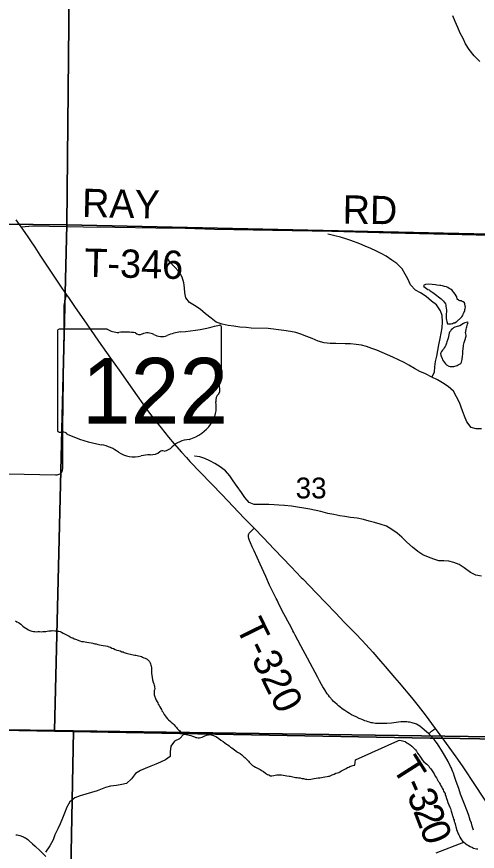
# Model space of a CAD drawing. Extents: x -8.8 to 41.4, y 0 to 34.6.
# Drawn here: x 7.271 to 8.197, y 18.372 to 20.049 of the extents above; entities that cross this region are included whole.
import ezdxf

# ---------------------------------------------------------------- set-up
doc = ezdxf.new("R2010")
doc.units = 0
for name, color, linetype in [('GM_X_City_Street', 7, 'Continuous'), ('GM_X_Corporation', 7, 'Continuous'), ('GM_X_Minor_Lake', 7, 'Continuous'), ('GM_X_Minor_River', 7, 'Continuous'), ('GM_X_Section_Text', 7, 'Continuous'), ('GM_X_State_Route', 7, 'Continuous'), ('GM_X_Township_Road', 7, 'Continuous'), ('GM_X_Township_Text', 7, 'Continuous'), ('GM_X_Unincorporated_Location', 7, 'Continuous')]:
    doc.layers.add(name, color=color, linetype=linetype)

msp = doc.modelspace()

# ---------------------------------------------------------------- linework, layer by layer
at = {"layer": 'GM_X_City_Street'}
for p, q in [((7.4526, 19.4206), (7.3561, 19.4206)), ((7.6825, 19.3209), (7.6825, 19.4256)), ((7.3529, 19.4172), (7.3529, 19.2171)), ((7.6824, 19.3209), (7.6825, 19.3209))]:
    msp.add_line(p, q, dxfattribs=at)
for centre, major_axis, start_param, end_param in [((7.3567, 19.4176), (0.00382, 0), 1.712693, 3.28349), ((7.4756, 19.4439), (0.037, 0), 4.042523, 4.731795), ((7.5651, 19.6935), (0.3495, 0), 4.814394, 5.042369), ((7.6788, 19.426), (0.00367, 0), 6.141152, 7.989035), ((7.4879, 19.3083), (0.133, 0), 1.404758, 1.657858), ((7.5181, 19.4187), (0.0107, 0), 3.836095, 5.185415), ((7.5338, 19.3955), (0.0222, 0), 0.950623, 2.079405), ((7.5624, 19.4273), (0.0267, 0), 4.081561, 5.145723), ((7.6096, 19.3595), (0.0703, 0), 1.699011, 2.107814), ((7.6785, 19.3205), (0.00393, 0), 5.05454, 6.418171), ((7.6816, 19.3132), (0.00568, 0), 1.883978, 3.671073), ((7.6455, 19.3), (0.0341, 0), 5.934695, 6.695948), ((7.6956, 19.2771), (0.0248, 0), 2.387724, 3.262537), ((7.5846, 19.2638), (0.0874, 0), 5.101752, 6.440018), ((7.3567, 19.2166), (0.00385, 0), 3.00124, 4.508301), ((7.3573, 19.2371), (0.0294, 0), 4.665946, 4.897461), ((7.3633, 19.2055), (0.0106, 0), 0.519207, 1.627899), ((7.4971, 19.3853), (0.2524, 0), 4.195997, 4.488961), ((7.4219, 19.1272), (0.079, 0), 0.823519, 1.323587), ((7.6215, 19.1609), (0.0479, 0), 1.647645, 2.488434), ((7.5073, 19.2045), (0.0501, 0), 4.026481, 4.996735), ((7.5362, 19.1353), (0.0412, 0), 1.495662, 1.94098), ((7.5399, 19.1896), (0.0267, 0), 4.691044, 5.507374), ((7.564, 19.1702), (0.00752, 0), 1.147584, 2.315152), ((7.5608, 19.1977), (0.0282, 0), 4.937069, 5.64225)]:
    msp.add_ellipse(centre, major_axis=major_axis, ratio=0.8, start_param=start_param, end_param=end_param, dxfattribs=at)
at = {"layer": 'GM_X_Corporation'}
for points in [[(6.8788, 18.6215), (8.1022, 18.5991), (8.1227, 18.5988), (8.3593, 18.595), (8.7626, 18.5884), (8.7926, 18.589), (8.8166, 18.5892), (8.8254, 18.5889), (8.8358, 18.5879), (8.8426, 18.587), (8.8536, 18.5853), (8.8632, 18.5843), (8.8658, 18.5843), (8.8715, 18.5846), (8.8767, 18.5853), (8.8942, 18.5896), (8.9, 18.5906), (8.9, 20.9)], [(6.3705, 18.3923), (6.3731, 18.628), (7.3471, 18.6145), (7.385, 18.614), (7.3641, 17.5315), (6.3609, 17.5464), (6.3656, 17.9584)], [(8.9, 14.1), (8.9, 18.5906), (8.8942, 18.5896), (8.8767, 18.5853), (8.8715, 18.5846), (8.8658, 18.5843), (8.8632, 18.5843), (8.8536, 18.5853), (8.8426, 18.587), (8.8358, 18.5879), (8.8254, 18.5889), (8.8166, 18.5892), (8.7926, 18.589), (8.7626, 18.5884), (8.3593, 18.595), (8.1227, 18.5988), (8.1022, 18.5991), (6.8788, 18.6215)]]:
    msp.add_lwpolyline(points, dxfattribs=at)
for points in [[(6.3701, 20.6506), (7.3817, 20.6407), (7.3719, 19.6303), (6.3565, 19.6406)], [(7.3817, 20.6407), (8.3787, 20.6214), (8.3714, 19.6082), (7.3719, 19.6303)], [(7.3719, 19.6303), (7.3471, 18.6145), (6.3731, 18.628), (6.3474, 18.629), (6.3565, 19.6406)], [(8.3714, 19.6082), (8.3651, 18.5999), (7.385, 18.614), (7.3471, 18.6145), (7.3719, 19.6303)], [(7.385, 18.614), (8.3651, 18.5999), (8.3581, 17.5144), (7.3641, 17.5315)]]:
    msp.add_lwpolyline(points, close=True, dxfattribs=at)
at = {"layer": 'GM_X_Minor_Lake'}
for points in [[(8.1561, 19.4365), (8.1641, 19.4433), (8.1661, 19.4455), (8.1673, 19.4477), (8.1685, 19.4504), (8.1693, 19.4526), (8.1718, 19.4579), (8.1718, 19.4601), (8.1727, 19.4624), (8.1731, 19.4647), (8.1728, 19.4673), (8.1721, 19.4715), (8.171, 19.4738), (8.1688, 19.4754), (8.1665, 19.4766), (8.1642, 19.4774), (8.1619, 19.4779), (8.1589, 19.4791), (8.1566, 19.481), (8.156, 19.4856), (8.1545, 19.4879), (8.1527, 19.4914), (8.1497, 19.4945), (8.1478, 19.4968), (8.1464, 19.4991), (8.143, 19.5011), (8.1407, 19.5027), (8.138, 19.5043), (8.135, 19.5059), (8.1312, 19.5067), (8.127, 19.508), (8.1239, 19.5084), (8.1213, 19.5085), (8.1159, 19.5094), (8.1128, 19.5098), (8.1059, 19.5108), (8.0979, 19.511), (8.0925, 19.5103), (8.089, 19.5085), (8.0893, 19.5062), (8.092, 19.5046), (8.0946, 19.5023), (8.0972, 19.5007), (8.1003, 19.4995), (8.1025, 19.4979), (8.1056, 19.496), (8.1078, 19.4944), (8.1131, 19.4905), (8.1157, 19.4881), (8.1191, 19.4858), (8.1214, 19.4838), (8.124, 19.4815), (8.127, 19.4791), (8.1292, 19.4768), (8.1307, 19.4744), (8.133, 19.4717), (8.1337, 19.4691), (8.134, 19.4668), (8.1349, 19.4588), (8.1346, 19.4482), (8.1342, 19.4455), (8.1345, 19.4421), (8.1352, 19.439), (8.1355, 19.436), (8.1373, 19.4318)], [(8.1373, 19.4318), (8.1396, 19.4313), (8.1419, 19.4316), (8.1442, 19.4316), (8.1469, 19.4323), (8.1492, 19.4334), (8.1515, 19.4337), (8.1547, 19.4355), (8.1561, 19.4365)], [(8.1617, 19.4275), (8.1612, 19.4272), (8.1589, 19.4265), (8.1566, 19.4262), (8.1519, 19.4248), (8.1492, 19.4233), (8.1469, 19.4215), (8.1445, 19.4196), (8.1429, 19.417), (8.1413, 19.4148), (8.1405, 19.4125), (8.1391, 19.4057), (8.1383, 19.4027), (8.1375, 19.4005), (8.1358, 19.3952), (8.1353, 19.3929), (8.1337, 19.3884), (8.1321, 19.3858), (8.1305, 19.3832), (8.1293, 19.3809), (8.1273, 19.3783), (8.1253, 19.3761), (8.1237, 19.3735), (8.1232, 19.3712), (8.1235, 19.3685), (8.1243, 19.3662), (8.1264, 19.3616), (8.1271, 19.3593), (8.1308, 19.3535), (8.1331, 19.3512), (8.1353, 19.3489), (8.1399, 19.3465), (8.1422, 19.3457), (8.1471, 19.3455), (8.1495, 19.3459), (8.1564, 19.348), (8.1588, 19.349), (8.1615, 19.3505), (8.1638, 19.352), (8.165, 19.3542), (8.1659, 19.3572), (8.1667, 19.3595), (8.1668, 19.3621), (8.1673, 19.3652), (8.1673, 19.3674), (8.1678, 19.3697), (8.168, 19.3769), (8.1684, 19.3803), (8.1685, 19.3826), (8.169, 19.386), (8.169, 19.3887), (8.1699, 19.3913), (8.1707, 19.3943), (8.1716, 19.3977), (8.1724, 19.4), (8.1741, 19.4045), (8.1745, 19.4067), (8.1746, 19.409), (8.1739, 19.4117), (8.1735, 19.414), (8.1736, 19.4163), (8.1745, 19.4208), (8.1753, 19.4234), (8.1758, 19.4257), (8.1766, 19.428), (8.1774, 19.4306), (8.1787, 19.434)], [(8.1787, 19.434), (8.1764, 19.4348), (8.1718, 19.4334), (8.1694, 19.4323), (8.1617, 19.4275)]]:
    msp.add_lwpolyline(points, dxfattribs=at)
at = {"layer": 'GM_X_Minor_River'}
for points in [[(8.202, 19.9587), (8.1904, 19.97), (8.1808, 19.9827), (8.1734, 19.9942), (8.1683, 20.0045), (8.1628, 20.0153), (8.1581, 20.0267), (8.1526, 20.039), (8.1479, 20.0501)], [(8.1053, 19.3246), (8.1108, 19.3344), (8.1118, 19.3453), (8.1127, 19.3559), (8.1156, 19.3665), (8.1173, 19.3782), (8.1194, 19.3896), (8.1223, 19.4017), (8.1244, 19.413), (8.1261, 19.4236), (8.1271, 19.4357), (8.1266, 19.4479), (8.1233, 19.4574), (8.1148, 19.4697), (8.1051, 19.4771), (8.0943, 19.4864), (8.083, 19.4935), (8.0729, 19.4993), (8.0628, 19.5101), (8.057, 19.5216), (8.0518, 19.5316), (8.0456, 19.542), (8.0352, 19.5528), (8.025, 19.5594), (8.0138, 19.5672), (8.0037, 19.5727), (7.9928, 19.5782), (7.9826, 19.583), (7.9717, 19.5877), (7.9608, 19.5921), (7.943, 19.5989), (7.9325, 19.6021), (7.9219, 19.6057), (7.9102, 19.6086), (7.8996, 19.6107), (7.8962, 19.6115)], [(8.2051, 19.2203), (8.1948, 19.2205), (8.1843, 19.2234), (8.1758, 19.2349), (8.1714, 19.246), (8.1671, 19.2567), (8.1609, 19.2735), (8.1554, 19.285), (8.1488, 19.2961), (8.1387, 19.3054), (8.1267, 19.3132), (8.117, 19.3187), (8.1053, 19.3246), (8.0929, 19.3309), (8.0813, 19.336), (8.0707, 19.3416), (8.0595, 19.3486), (8.0497, 19.3537), (8.0384, 19.3592), (8.0271, 19.3644), (8.0162, 19.3691), (8.0057, 19.3739), (7.9948, 19.3783), (7.9846, 19.3822), (7.9744, 19.3858), (7.9642, 19.3883), (7.9532, 19.39), (7.9419, 19.391), (7.9316, 19.3912), (7.9127, 19.3919), (7.9009, 19.3921), (7.8892, 19.3931), (7.8767, 19.3968), (7.8651, 19.4019), (7.8545, 19.4063), (7.8421, 19.4107), (7.8319, 19.4139), (7.8217, 19.416), (7.8081, 19.4178), (7.7971, 19.4195), (7.7872, 19.4208), (7.7766, 19.4222), (7.7425, 19.4228), (7.7323, 19.4238), (7.7194, 19.4248), (7.7073, 19.4265), (7.6963, 19.4278), (7.6838, 19.4307), (7.6722, 19.4351), (7.6617, 19.4429), (7.6508, 19.4518), (7.6396, 19.4608), (7.6284, 19.4682), (7.6182, 19.4741), (7.6112, 19.4837), (7.6091, 19.4936), (7.6085, 19.5038), (7.6072, 19.5137), (7.6036, 19.5252), (7.5977, 19.5359), (7.5873, 19.5464), (7.5784, 19.5568), (7.5721, 19.5667), (7.5706, 19.5679)], [(8.2057, 18.9248), (8.194, 18.9266), (8.1831, 18.9317), (8.1704, 18.941), (8.1606, 18.948), (8.1501, 18.952), (8.1399, 18.9549), (8.1296, 18.9551), (8.1198, 18.9556), (8.1096, 18.9585), (8.0987, 18.9625), (8.0874, 18.9672), (8.0776, 18.9739), (8.0668, 18.9828), (8.0556, 18.9929), (8.0455, 19.0029), (8.0358, 19.0111), (8.0249, 19.0185), (8.0141, 19.0251), (8.0016, 19.0291), (7.9903, 19.0324), (7.9797, 19.0352), (7.968, 19.0381), (7.9552, 19.041), (7.9423, 19.0424), (7.9309, 19.0441), (7.9203, 19.0458), (7.9082, 19.0483), (7.8965, 19.0505), (7.8822, 19.0541), (7.8603, 19.0591), (7.8482, 19.0612), (7.8357, 19.063), (7.8232, 19.0651), (7.8096, 19.0665), (7.7982, 19.0671), (7.7887, 19.0676), (7.7781, 19.0682), (7.7686, 19.0688), (7.7591, 19.0686), (7.7481, 19.0684), (7.7383, 19.0728), (7.7294, 19.0828), (7.7231, 19.0928), (7.7139, 19.1043), (7.7061, 19.1162), (7.6995, 19.1258), (7.6905, 19.1358), (7.6801, 19.144), (7.6692, 19.151), (7.6591, 19.1565), (7.6493, 19.1609), (7.6391, 19.1641), (7.6292, 19.1654), (7.6285, 19.1655)], [(7.2684, 18.8349), (7.2713, 18.8329), (7.2743, 18.8313), (7.2765, 18.83), (7.2791, 18.828), (7.281, 18.8261), (7.2835, 18.8241), (7.2861, 18.8217), (7.2891, 18.8197), (7.2943, 18.8164), (7.2973, 18.8152), (7.3014, 18.8139), (7.3044, 18.8134), (7.307, 18.8133), (7.3097, 18.8128), (7.3135, 18.8135), (7.3165, 18.813), (7.3199, 18.8128), (7.3233, 18.8131), (7.3264, 18.813), (7.3294, 18.8133), (7.3321, 18.8139), (7.3355, 18.8146), (7.3378, 18.8145), (7.3404, 18.8148), (7.3424, 18.8151), (7.3477, 18.8149), (7.3499, 18.8144), (7.3529, 18.8139), (7.3556, 18.8138), (7.3582, 18.813), (7.3612, 18.8121), (7.3645, 18.8101), (7.3712, 18.8068), (7.3738, 18.8052), (7.3765, 18.8039), (7.3805, 18.8015), (7.3835, 18.8003), (7.3865, 18.7986), (7.3891, 18.7978), (7.3981, 18.7944), (7.4011, 18.7935), (7.4049, 18.7934), (7.4083, 18.7925), (7.412, 18.792), (7.4158, 18.7911), (7.4203, 18.7902), (7.4237, 18.7897), (7.4282, 18.7887), (7.4309, 18.7883), (7.4339, 18.7874), (7.4372, 18.7865), (7.441, 18.7856), (7.4448, 18.7851), (7.4493, 18.7842), (7.4531, 18.7836), (7.4561, 18.7828), (7.4594, 18.7815), (7.462, 18.7799), (7.4654, 18.779), (7.4688, 18.7774), (7.4721, 18.7761), (7.4763, 18.7748), (7.4789, 18.7743), (7.4822, 18.7727), (7.4849, 18.7722), (7.4871, 18.7714), (7.4909, 18.7697), (7.4939, 18.7688), (7.4961, 18.7684), (7.4999, 18.7675), (7.5048, 18.7665), (7.5082, 18.766), (7.5104, 18.766), (7.5134, 18.7651), (7.5157, 18.7646), (7.5191, 18.7637), (7.5217, 18.7629), (7.5239, 18.762), (7.5265, 18.7604), (7.5292, 18.7596), (7.5329, 18.7579), (7.538, 18.7532), (7.5391, 18.7504), (7.5398, 18.7485), (7.5408, 18.7458), (7.5415, 18.7435), (7.5418, 18.7412), (7.5417, 18.7385)], [(7.5417, 18.7385), (7.5419, 18.7344), (7.5421, 18.7298), (7.5433, 18.7206), (7.5436, 18.7164), (7.5453, 18.7118), (7.5463, 18.7083), (7.547, 18.7056), (7.5477, 18.7033), (7.548, 18.7014), (7.5483, 18.6987), (7.5478, 18.6964), (7.5473, 18.6942), (7.5471, 18.6881), (7.5474, 18.6858), (7.5505, 18.6769), (7.5516, 18.675), (7.5534, 18.6719), (7.5548, 18.6699), (7.5555, 18.6676), (7.5573, 18.6645), (7.5587, 18.6618), (7.5609, 18.6583), (7.5619, 18.6563), (7.563, 18.654), (7.5644, 18.6517), (7.5658, 18.649), (7.5673, 18.6463), (7.5691, 18.6439), (7.5712, 18.6412), (7.5742, 18.638), (7.5764, 18.636), (7.5793, 18.6329), (7.5815, 18.6313), (7.5848, 18.6285), (7.587, 18.6261), (7.5899, 18.6222), (7.5921, 18.6202), (7.5936, 18.6183), (7.5969, 18.6151), (7.5991, 18.6135), (7.6009, 18.6111), (7.6031, 18.6095), (7.6068, 18.6071), (7.6095, 18.607), (7.6117, 18.6066), (7.6147, 18.6057), (7.6174, 18.6052), (7.6207, 18.6043), (7.6241, 18.6031), (7.6282, 18.6018), (7.6308, 18.6005), (7.6331, 18.6001), (7.6357, 18.5996), (7.6384, 18.5999), (7.6414, 18.6002), (7.6438, 18.6012), (7.648, 18.603), (7.6526, 18.6047), (7.6564, 18.6057), (7.6591, 18.606), (7.6617, 18.6059), (7.6666, 18.6042), (7.6692, 18.603), (7.6714, 18.6021), (7.6744, 18.6005), (7.6774, 18.5985), (7.6811, 18.5949), (7.6859, 18.5921), (7.6896, 18.5897), (7.6925, 18.5869), (7.6955, 18.5853), (7.6981, 18.5833), (7.701, 18.5812), (7.7033, 18.5796), (7.7114, 18.5733), (7.7147, 18.5709), (7.7173, 18.5696), (7.7203, 18.568), (7.7232, 18.5652), (7.7273, 18.5616), (7.7295, 18.56), (7.7313, 18.5581), (7.7342, 18.5553), (7.7368, 18.5529), (7.7386, 18.5506), (7.7415, 18.5474), (7.7452, 18.5442), (7.7478, 18.543), (7.7508, 18.541), (7.7549, 18.5386), (7.7579, 18.5373), (7.7605, 18.5357), (7.7642, 18.5333), (7.7668, 18.532), (7.7708, 18.5285), (7.7749, 18.526), (7.7779, 18.5252), (7.7813, 18.5235), (7.7839, 18.5234), (7.7881, 18.5237)], [(7.6068, 18.6071), (7.5983, 18.5975), (7.5884, 18.5931), (7.5806, 18.583), (7.5796, 18.5713), (7.5794, 18.5618), (7.5698, 18.5552), (7.5603, 18.5508), (7.5503, 18.5464), (7.5408, 18.5428), (7.5293, 18.5381), (7.5197, 18.5337), (7.5098, 18.5282), (7.5016, 18.517), (7.4916, 18.5081), (7.482, 18.5056), (7.4714, 18.5039), (7.4596, 18.5022), (7.4497, 18.5001), (7.4325, 18.4933), (7.421, 18.4897), (7.4096, 18.4865), (7.3985, 18.4833), (7.3878, 18.4793), (7.3778, 18.4711), (7.3719, 18.4606), (7.3668, 18.4482), (7.3628, 18.4384), (7.358, 18.4271), (7.3533, 18.4166), (7.3477, 18.405), (7.3441, 18.3944), (7.3375, 18.3828), (7.3289, 18.3697)], [(7.7881, 18.5237), (7.7908, 18.5243), (7.7938, 18.525), (7.7961, 18.5253), (7.8033, 18.525), (7.8067, 18.5245), (7.8105, 18.524), (7.8142, 18.5231), (7.8184, 18.5226), (7.8206, 18.5225), (7.8263, 18.5211), (7.8312, 18.5202), (7.8349, 18.5197), (7.8376, 18.5192), (7.8406, 18.5191), (7.8444, 18.5182), (7.8478, 18.5177), (7.8515, 18.5168), (7.8542, 18.5167), (7.8576, 18.5162), (7.8621, 18.5164), (7.8659, 18.517), (7.869, 18.518), (7.8732, 18.5187), (7.877, 18.5193), (7.8804, 18.5195), (7.8839, 18.5202), (7.8869, 18.5208), (7.8907, 18.5214), (7.8949, 18.5217), (7.8976, 18.5223), (7.8995, 18.5227), (7.9022, 18.5241), (7.9053, 18.5251), (7.9091, 18.5269), (7.9126, 18.5283), (7.9156, 18.5293), (7.9183, 18.5303), (7.9206, 18.5314), (7.9241, 18.5332), (7.9303, 18.5368), (7.933, 18.5382), (7.9357, 18.54), (7.9388, 18.541), (7.9407, 18.5421), (7.9426, 18.5424), (7.9491, 18.5445), (7.951, 18.5448), (7.9522, 18.5554), (8.0369, 18.5938), (8.0388, 18.5945), (8.0415, 18.5948), (8.0438, 18.5943), (8.0468, 18.5938), (8.049, 18.593), (8.052, 18.5921), (8.0553, 18.5897), (8.0579, 18.5881), (8.062, 18.5857), (8.065, 18.5829), (8.069, 18.5797), (8.0727, 18.5758), (8.0745, 18.5727), (8.077, 18.5688), (8.0795, 18.5652), (8.0813, 18.5625), (8.0838, 18.5586), (8.086, 18.5551), (8.0893, 18.5516), (8.0926, 18.5488), (8.0955, 18.5464), (8.0977, 18.5444), (8.0992, 18.5424), (8.101, 18.5401), (8.1032, 18.5373), (8.1075, 18.5311), (8.11, 18.5272), (8.1125, 18.5229), (8.1146, 18.519), (8.1168, 18.5155), (8.1186, 18.5128), (8.1197, 18.5109), (8.1207, 18.5085), (8.1222, 18.5062), (8.1236, 18.5035), (8.1254, 18.5008), (8.1264, 18.4984), (8.1282, 18.4949), (8.1293, 18.4926), (8.1303, 18.4907), (8.1321, 18.4876), (8.1324, 18.4857), (8.1334, 18.4822), (8.1352, 18.4779), (8.1366, 18.4741), (8.1379, 18.4695), (8.1418, 18.4602), (8.1428, 18.4579), (8.1445, 18.4521), (8.1455, 18.4483), (8.1465, 18.4452)], [(8.1465, 18.4452), (8.1472, 18.4433), (8.1482, 18.4394), (8.1493, 18.4363), (8.1503, 18.434), (8.1506, 18.4317), (8.1517, 18.429), (8.1523, 18.4267), (8.153, 18.4236), (8.1536, 18.4209), (8.1543, 18.4186), (8.1554, 18.4155), (8.1564, 18.4121), (8.1578, 18.409), (8.1584, 18.4067), (8.1595, 18.4044), (8.1609, 18.402), (8.1616, 18.4001), (8.1638, 18.3966), (8.1649, 18.3946), (8.1674, 18.3923), (8.17, 18.3903), (8.1766, 18.3847), (8.1792, 18.3831), (8.1826, 18.3814), (8.1871, 18.3794), (8.1893, 18.3782), (8.1953, 18.3764), (8.1979, 18.3763)], [(8.1143, 18.3687), (8.17, 18.3903)]]:
    msp.add_lwpolyline(points, dxfattribs=at)
at = {"layer": 'GM_X_State_Route'}
for points in [[(7.2693, 19.6407), (7.2795, 19.6264), (7.292, 19.6081), (7.2986, 19.5984), (7.3072, 19.5854), (7.3177, 19.5693), (7.3241, 19.5594), (7.3511, 19.5191), (7.3618, 19.5031), (7.3711, 19.4896), (7.3748, 19.4841), (7.3872, 19.4663), (7.4116, 19.431), (7.4355, 19.3969), (7.4593, 19.3627), (7.4767, 19.3385), (7.5131, 19.2866), (7.5361, 19.2549), (7.5469, 19.2405), (7.5611, 19.2224), (7.5764, 19.2036), (7.5876, 19.1903), (7.6024, 19.1735), (7.612, 19.1631), (7.6192, 19.1551), (7.6406, 19.1325), (7.6838, 19.0878), (7.7285, 19.0413), (7.7482, 19.021), (7.767, 19.0015), (7.7887, 18.9784), (7.8228, 18.9432), (7.8431, 18.9221), (7.8461, 18.9189), (7.8732, 18.8907), (7.9117, 18.851), (7.9302, 18.8317), (7.9376, 18.8242), (7.9519, 18.8095), (7.9654, 18.795), (7.9867, 18.7715), (8.0024, 18.7539), (8.012, 18.7427), (8.0307, 18.7209), (8.0396, 18.7104), (8.0507, 18.6972), (8.0573, 18.6892), (8.0646, 18.6804), (8.0782, 18.6639), (8.0919, 18.6458), (8.1125, 18.6187), (8.1259, 18.6001)], [(8.1259, 18.6001), (8.1539, 18.5613), (8.1664, 18.5435), (8.1942, 18.5016), (8.2069, 18.4824), (8.2395, 18.4332), (8.2676, 18.3914)]]:
    msp.add_lwpolyline(points, dxfattribs=at)
at = {"layer": 'GM_X_Township_Road'}
msp.add_line((8.1065, 18.6006), (8.1059, 18.6011), dxfattribs=at)
for points in [[(7.2795, 19.6264), (7.2882, 19.6272), (7.295, 19.6279), (7.3025, 19.6281), (7.405, 19.6264), (7.4683, 19.6254), (7.5503, 19.6246), (7.6093, 19.6234), (7.6689, 19.6216), (7.785, 19.6199), (7.9042, 19.6174), (8.0241, 19.6145), (8.2514, 19.609), (8.3768, 19.6058), (8.3929, 19.6052), (8.4257, 19.604), (8.4296, 19.6039)], [(7.2365, 19.13), (7.2861, 19.1293), (7.3489, 19.1278), (7.352, 19.1281), (7.3544, 19.1285), (7.3563, 19.1292), (7.358, 19.1302), (7.3594, 19.1313), (7.3604, 19.1324), (7.3613, 19.1337), (7.3624, 19.1355), (7.3631, 19.1377), (7.3636, 19.141), (7.3639, 19.1447), (7.3638, 19.1811), (7.3639, 19.2227), (7.3648, 19.3191), (7.3654, 19.3737), (7.3661, 19.4241), (7.3665, 19.4657), (7.3666, 19.4688), (7.3669, 19.4718), (7.3676, 19.4756), (7.3686, 19.4797), (7.3711, 19.4896)], [(8.1059, 18.6011), (8.1043, 18.6028), (8.1016, 18.6054), (8.099, 18.608), (8.0945, 18.612), (8.0864, 18.6191), (8.0816, 18.6229), (8.0779, 18.6253), (8.0746, 18.627), (8.0706, 18.6287), (8.0683, 18.6294), (8.0659, 18.6301), (8.0634, 18.6307), (8.0604, 18.6312), (8.0582, 18.6314), (8.0554, 18.6317), (8.0498, 18.6318), (8.043, 18.6315), (8.0245, 18.6294), (8.0152, 18.6286), (8.0111, 18.6283), (8.006, 18.6281), (7.999, 18.6282), (7.9925, 18.6287), (7.9892, 18.6291), (7.9864, 18.6296), (7.9836, 18.6301), (7.9804, 18.631), (7.9772, 18.6319), (7.9739, 18.633), (7.9707, 18.6341), (7.9667, 18.6356), (7.9633, 18.6371), (7.9595, 18.6387), (7.9532, 18.6417), (7.9484, 18.6439), (7.9442, 18.6461), (7.9403, 18.6482), (7.9364, 18.6505), (7.9305, 18.6543), (7.9251, 18.6582), (7.9204, 18.6618), (7.9176, 18.664), (7.9149, 18.6664), (7.9103, 18.6706), (7.9081, 18.6729), (7.9061, 18.6751), (7.9001, 18.6823), (7.8978, 18.6851), (7.8954, 18.6882), (7.8904, 18.696), (7.8867, 18.7018), (7.8835, 18.707), (7.8798, 18.714), (7.8762, 18.7207), (7.8556, 18.7596), (7.8424, 18.7842), (7.8359, 18.7962), (7.8308, 18.8061), (7.8282, 18.811), (7.8262, 18.8149), (7.8233, 18.8204), (7.8192, 18.8281), (7.816, 18.8341), (7.8114, 18.8429), (7.8082, 18.849), (7.8036, 18.8578), (7.7966, 18.8716), (7.7944, 18.876), (7.7924, 18.8799), (7.7867, 18.8916), (7.7793, 18.9067), (7.7716, 18.9237), (7.7604, 18.9486), (7.7541, 18.9621), (7.7481, 18.9751), (7.7446, 18.9831), (7.7408, 18.9916), (7.7389, 18.9962), (7.7382, 18.9982), (7.7377, 19.0003), (7.7371, 19.0034), (7.737, 19.0058), (7.7372, 19.0077), (7.7378, 19.0094), (7.7386, 19.0111), (7.7402, 19.0129), (7.7482, 19.021)], [(8.099, 18.608), (8.1015, 18.61), (8.105, 18.6128), (8.1086, 18.6157), (8.1125, 18.6187)], [(8.1465, 18.5344), (8.1448, 18.5388), (8.1433, 18.5418), (8.1383, 18.5518), (8.1312, 18.5649), (8.1253, 18.5751), (8.1192, 18.5845), (8.117, 18.5876), (8.1145, 18.591), (8.1124, 18.5937), (8.1102, 18.5963), (8.1065, 18.6006)], [(8.1894, 18.4144), (8.1869, 18.4224), (8.185, 18.4281), (8.1829, 18.4345), (8.1798, 18.4433), (8.177, 18.4509), (8.1744, 18.4575), (8.1723, 18.4628), (8.1684, 18.4733), (8.1635, 18.4866), (8.1595, 18.4975), (8.1547, 18.5116), (8.1512, 18.5217), (8.1488, 18.5285), (8.1477, 18.5316), (8.1465, 18.5344)], [(7.2689, 18.4048), (7.2715, 18.4044), (7.2742, 18.4039), (7.277, 18.4032), (7.2791, 18.4026), (7.2807, 18.4021), (7.2827, 18.4014), (7.2847, 18.4005), (7.2867, 18.3995), (7.2884, 18.3985), (7.2905, 18.3971), (7.2933, 18.3951), (7.2962, 18.3928), (7.3029, 18.3866), (7.3079, 18.3819), (7.3178, 18.3726), (7.3293, 18.3612)]]:
    msp.add_lwpolyline(points, dxfattribs=at)

# ---------------------------------------------------------------- texts
at = {"layer": 'GM_X_City_Street'}
msp.add_text('122', height=0.13184, dxfattribs=at).set_placement((7.4019, 19.2312))
at = {"layer": 'GM_X_Section_Text'}
for s, height, rotation, p in [('RAY', 0.05682, 358.6988, (7.4018, 19.6464)), ('RD', 0.05682, 359.0128, (7.9258, 19.6331)), ('T-346', 0.05682, 358.5967, (7.4064, 19.5262)), ('T-320', 0.05682, 296.1876, (7.7103, 18.8229)), ('T', 0.0568, 302.4574, (8.024, 18.54)), ('3', 0.0568, 291.0409, (8.0549, 18.4854)), ('-', 0.0568, 293.8131, (8.0458, 18.5061)), ('2', 0.0568, 290.9577, (8.0675, 18.4528)), ('0', 0.0568, 290.9404, (8.08, 18.4201))]:
    msp.add_text(s, height=height, rotation=rotation, dxfattribs=at).set_placement(p)
at = {"layer": 'GM_X_Township_Text'}
msp.add_text('33', height=0.04186, rotation=0, dxfattribs=at).set_placement((7.8317, 19.0807))
at = {"layer": 'GM_X_Unincorporated_Location'}
for s in ['s', 'r']:
    msp.add_text(s, height=0.000189, dxfattribs=at).set_placement((7.514, 19.3038))
msp.add_text('122', height=0.000189, rotation=0, dxfattribs=at).set_placement((7.4471, 19.2901))

doc.saveas('drawing.dxf')
